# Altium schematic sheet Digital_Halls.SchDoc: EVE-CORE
size A4; Organization: Ingenia Motion Control; Address1: Carrer Avila, 124, 2B; Address2: 08018 Barcelona Spain; Address3: www.ingeniamc.com; Address4: www.ingeniamc.com; Documentation: https://doc.ingeniamc.com/x/coAZBg
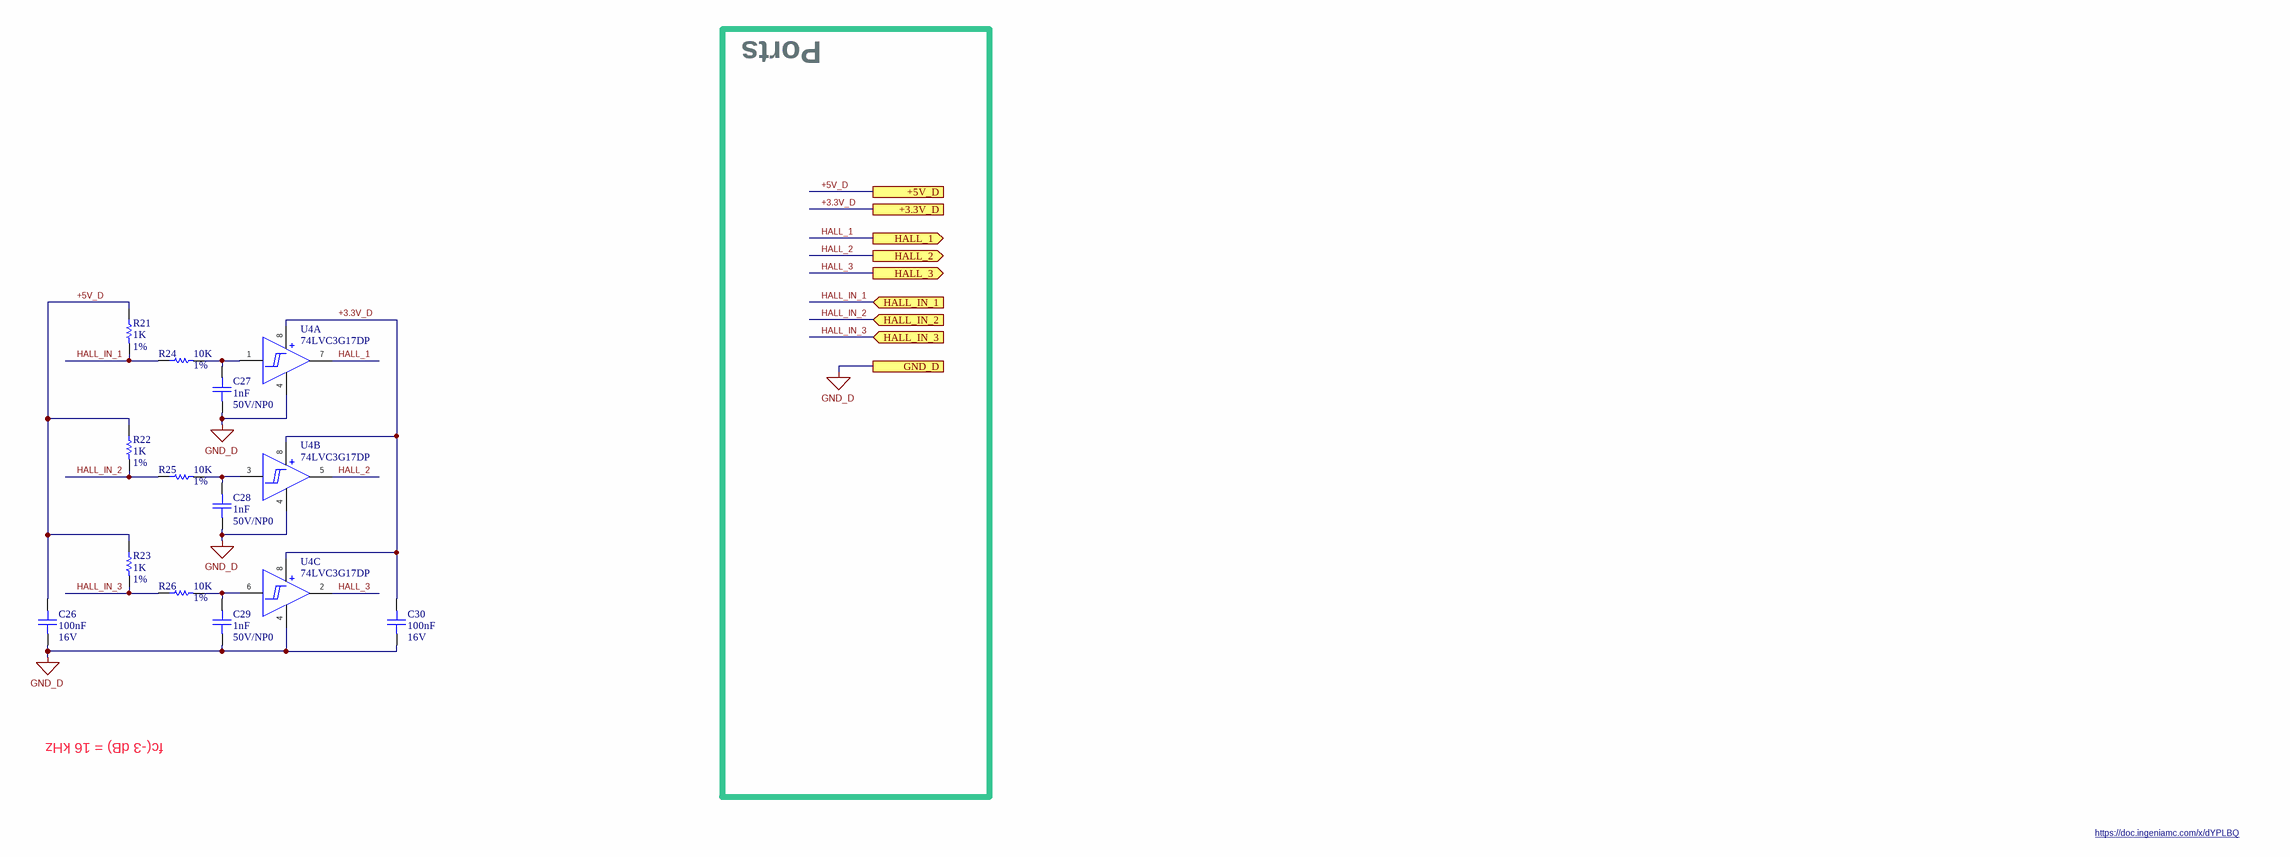
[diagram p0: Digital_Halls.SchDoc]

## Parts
C26  value 100nF  Voltage: 16V  [C_0402]  (hidden comment: C_0402--100nF--16V)
C27  value 1nF  Voltage: 50V/NP0  [C_0402]  (hidden comment: C_0402--1nF--50V/NP0)
C28  value 1nF  Voltage: 50V/NP0  [C_0402]  (hidden comment: C_0402--1nF--50V/NP0)
C29  value 1nF  Voltage: 50V/NP0  [C_0402]  (hidden comment: C_0402--1nF--50V/NP0)
C30  value 100nF  Voltage: 16V  [C_0402]  (hidden comment: C_0402--100nF--16V)
R21  value 1K  Tolerance: 1%  [R_0402]  (hidden comment: R_0402--1K--1%)
R22  value 1K  Tolerance: 1%  [R_0402]  (hidden comment: R_0402--1K--1%)
R23  value 1K  Tolerance: 1%  [R_0402]  (hidden comment: R_0402--1K--1%)
R24  value 10K  Tolerance: 1%  [R_0402]  (hidden comment: R_0402--10K--1%)
R25  value 10K  Tolerance: 1%  [R_0402]  (hidden comment: R_0402--10K--1%)
R26  value 10K  Tolerance: 1%  [R_0402]  (hidden comment: R_0402--10K--1%)
U4  74LVC3G17DP  [MSOP8_3x3_065P]  (parts A,B,C of 3)

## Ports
+3.3V_D, +5V_D, GND_D, HALL_1 (out), HALL_2 (out), HALL_3 (out), HALL_IN_1 (in), HALL_IN_2 (in), HALL_IN_3 (in)

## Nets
GND_D: C26.2 C27.2 C28.2 C29.2 C30.2 U4.4(GND) ; port GND_D
+3.3V_D: C30.1 U4.8(Vcc) ; port +3.3V_D
+5V_D: C26.1 R21.1 R22.1 R23.1 ; port +5V_D
HALL_1: U4.7(1Y) ; port HALL_1
HALL_2: U4.5(2Y) ; port HALL_2
HALL_3: U4.2(3Y) ; port HALL_3
HALL_IN_1: R21.2 R24.1 ; port HALL_IN_1
HALL_IN_2: R22.2 R25.1 ; port HALL_IN_2
HALL_IN_3: R23.2 R26.1 ; port HALL_IN_3
NetC27_1: C27.1 R24.2 U4.1(1A)
NetC28_1: C28.1 R25.2 U4.3(2A)
NetC29_1: C29.1 R26.2 U4.6(3A)

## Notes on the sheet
- Ports
- fc(-3 dB) = 16 kHz
- https://doc.ingeniamc.com/x/dYPLBQ

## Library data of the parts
C26 C30 = C_0402[[/\]]100nF[[/\]]16V: CAP CER 100nF 16V X7R 0402; ManufacturerName: Murata; ManufacturerPN: GRM155R71C104KA88D; AlternativeManufacturer: Wurth; IsPreferred: 1; IngeniaID: 672; InternalStock: 0; TemperatureMaxC: 125; TemperatureMinC: -55; MTBF55h: 36129613; AlternativePN: 885012205037
C27-C29 = C_0402[[/\]]1nF[[/\]]50V/NP0: MLCC, 0402, NP0, 50V, 1NF, 5%; ManufacturerName: TDK; ManufacturerPN: C1005NP01H102J050BA; AlternativeManufacturer: Murata; IsPreferred: 0; IsGeneric: 1; IngeniaID: 1899; TemperatureMaxC: 125; TemperatureMinC: -55; MTBF55h: 59960233; AlternativePN: GRM1555C1H102GA01D
R21-R23 = R_0402[[/\]]1K[[/\]]1%: RES 1K OHM 1/16W 1% 0402 SMD; ManufacturerName: Panasonic Electronic Components; ManufacturerPN: ERJ-2RKF1001X; AlternativeManufacturer: Bourns; IsPreferred: 0; IsGeneric: 1; IngeniaID: 686; TemperatureMaxC: 155; TemperatureMinC: -55; MTBF55h: 91649788; AlternativePN: CR0402-FX-1001GLF
R24-R26 = R_0402[[/\]]10K[[/\]]1%: RESISTOR 10K OHM 1/16W 1% 0402 SMD; ManufacturerName: Stackpole Electronics; ManufacturerPN: RMCF0402FT10K0; AlternativeManufacturer: Vishay Dale; IsPreferred: 0; IsGeneric: 1; IngeniaID: 685; TemperatureMaxC: 155; TemperatureMinC: -55; MTBF55h: 91649788; AlternativePN: CRCW040210K0FKED
U4 = 74LVC3G17DP: Schmitt Trigger Buffer Triple non-inverting 8TSSOP 125ºC; ManufacturerName: NXP; ManufacturerPN: 74LVC3G17DP,125; IsPreferred: 1; IsGeneric: 0; IngeniaID: 2453; TemperatureMaxC: 125; TemperatureMinC: -40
